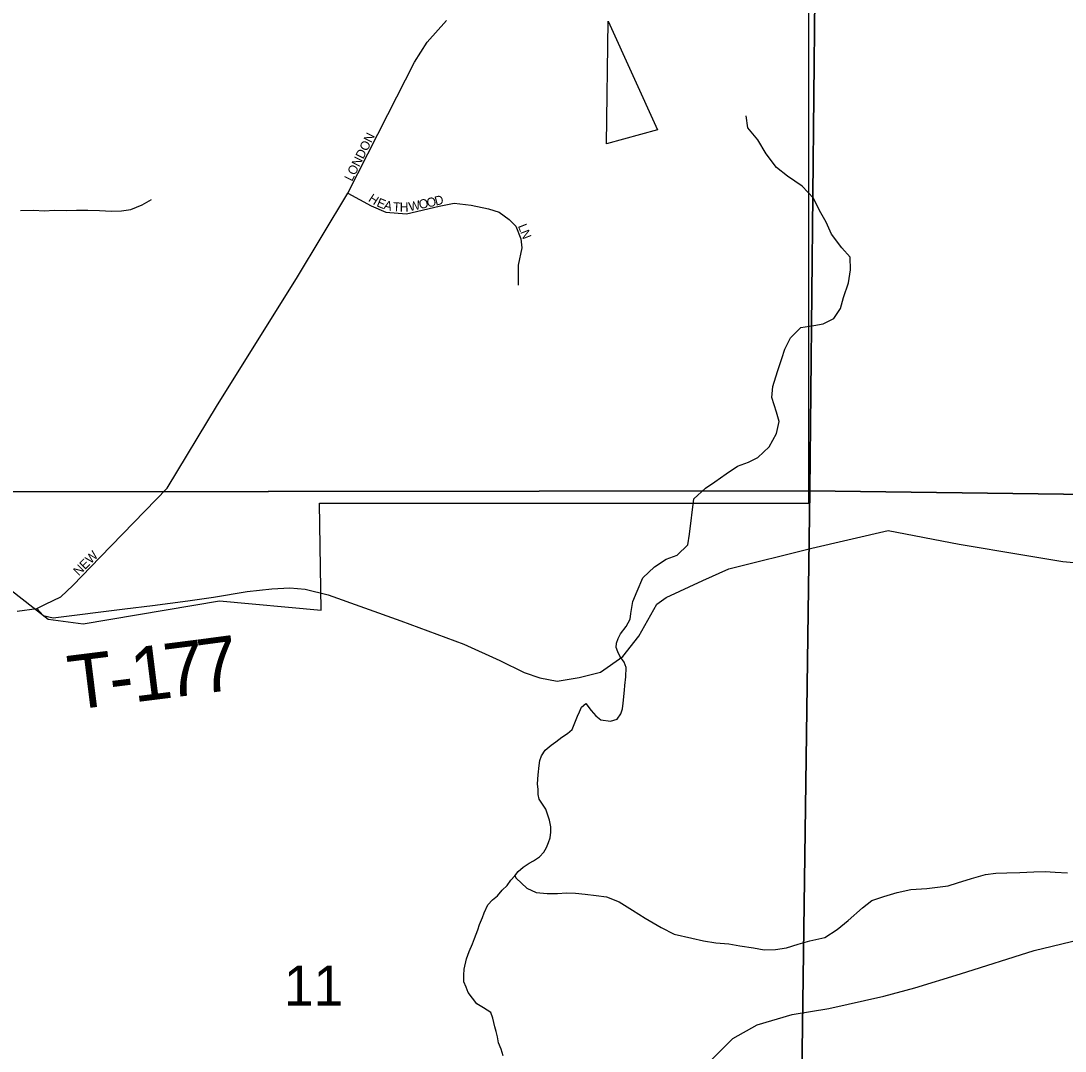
# Model space of a CAD drawing. Extents: x 0 to 34, y -2.3 to 22.
# Drawn here: x 6.815 to 7.907, y 18.764 to 19.84 of the extents above; entities that cross this region are included whole.
import ezdxf

# ---------------------------------------------------------------- set-up
doc = ezdxf.new("R2010")
doc.units = 0
for name, color, linetype in [('GM_X_City_Street', 7, 'Continuous'), ('GM_X_City_Street_Text', 7, 'Continuous'), ('GM_X_Corporation', 7, 'Continuous'), ('GM_X_County_Road', 7, 'Continuous'), ('GM_X_Minor_River', 7, 'Continuous'), ('GM_X_Section', 7, 'Continuous'), ('GM_X_Section_Text', 7, 'Continuous'), ('GM_X_Township_Road', 7, 'Continuous'), ('GM_X_Township_Road_Text', 7, 'Continuous')]:
    doc.layers.add(name, color=color, linetype=linetype)

msp = doc.modelspace()

# ---------------------------------------------------------------- linework, layer by layer
at = {"layer": 'GM_X_City_Street'}
for p, q in [((7.2401, 19.8181), (7.2603, 19.8406)), ((7.2266, 19.7972), (7.2401, 19.8181)), ((7.1989, 19.7426), (7.2266, 19.7972)), ((7.1572, 19.6603), (7.1989, 19.7426)), ((7.1034, 19.5711), (7.1572, 19.6603)), ((7.1572, 19.6603), (7.1815, 19.647)), ((7.1815, 19.647), (7.1969, 19.6405)), ((7.1969, 19.6405), (7.2182, 19.6386)), ((7.2182, 19.6386), (7.2526, 19.6466)), ((7.2526, 19.6466), (7.2681, 19.6498)), ((7.2681, 19.6498), (7.2859, 19.6478)), ((7.2859, 19.6478), (7.304, 19.6438)), ((7.304, 19.6438), (7.3153, 19.6403)), ((7.3153, 19.6403), (7.3257, 19.6328)), ((7.3257, 19.6328), (7.3327, 19.6257)), ((7.3327, 19.6257), (7.3377, 19.6126)), ((7.3377, 19.6126), (7.339, 19.6031)), ((7.339, 19.6031), (7.3351, 19.5851)), ((7.3351, 19.5851), (7.3351, 19.5642)), ((7.0209, 19.4392), (7.1034, 19.5711)), ((6.9683, 19.3521), (7.0209, 19.4392)), ((6.8982, 19.2799), (6.9683, 19.3521)), ((6.8698, 19.2501), (6.8982, 19.2799)), ((6.8573, 19.2385), (6.8698, 19.2501)), ((6.8413, 19.2307), (6.8573, 19.2385))]:
    msp.add_line(p, q, dxfattribs=at)
at = {"layer": 'GM_X_Corporation'}
for points in [[(6.7701, 19.2725), (6.8438, 19.2151), (6.8806, 19.2101), (7.0229, 19.2342), (7.1292, 19.2244), (7.1274, 19.3364), (7.6387, 19.3364), (7.6388, 20.075), (7.7148, 20.075), (7.7148, 20.217), (7.7814, 20.2892), (7.8572, 20.3839), (7.8729, 20.4123), (7.9045, 20.4123), (7.8951, 20.4454), (7.9466, 20.4977)], [(7.429, 19.8401), (7.4807, 19.7264), (7.4275, 19.7119), (7.429, 19.8401)]]:
    msp.add_lwpolyline(points, dxfattribs=at)
at = {"layer": 'GM_X_County_Road'}
for p, q in [((6.8116, 19.2234), (6.8322, 19.2262)), ((6.8322, 19.2262), (6.8413, 19.2307))]:
    msp.add_line(p, q, dxfattribs=at)
at = {"layer": 'GM_X_Minor_River'}
for p, q in [((7.5749, 19.7285), (7.5734, 19.7411)), ((7.5855, 19.716), (7.5749, 19.7285)), ((7.5941, 19.7013), (7.5855, 19.716)), ((7.605, 19.6873), (7.5941, 19.7013)), ((7.6165, 19.6782), (7.605, 19.6873)), ((7.6317, 19.6675), (7.6165, 19.6782)), ((7.6435, 19.655), (7.6317, 19.6675)), ((6.9422, 19.648), (6.9518, 19.6537)), ((7.6499, 19.6422), (7.6435, 19.655)), ((6.815, 19.6421), (6.8286, 19.6424)), ((6.8286, 19.6424), (6.84, 19.642)), ((6.84, 19.642), (6.8503, 19.6425)), ((6.8503, 19.6425), (6.8635, 19.6421)), ((6.8635, 19.6421), (6.8734, 19.6425)), ((6.8734, 19.6425), (6.8855, 19.6425)), ((6.8855, 19.6425), (6.8976, 19.6421)), ((6.8976, 19.6421), (6.9101, 19.6414)), ((6.9101, 19.6414), (6.9204, 19.6418)), ((6.9204, 19.6418), (6.9303, 19.6434)), ((6.9303, 19.6434), (6.9422, 19.648)), ((7.6567, 19.6299), (7.6499, 19.6422)), ((7.6624, 19.6176), (7.6567, 19.6299)), ((7.6733, 19.6032), (7.6624, 19.6176)), ((7.6821, 19.5934), (7.6733, 19.6032)), ((7.6824, 19.5801), (7.6821, 19.5934)), ((7.6801, 19.5665), (7.6824, 19.5801)), ((7.6751, 19.5511), (7.6801, 19.5665)), ((7.6717, 19.5398), (7.6751, 19.5511)), ((7.6649, 19.5294), (7.6717, 19.5398)), ((7.6305, 19.5198), (7.6438, 19.5221)), ((7.6438, 19.5221), (7.6537, 19.5237)), ((7.6537, 19.5237), (7.6649, 19.5294)), ((7.6195, 19.5092), (7.6305, 19.5198)), ((7.6138, 19.4972), (7.6195, 19.5092)), ((7.6059, 19.4739), (7.6105, 19.4874)), ((7.6105, 19.4874), (7.6138, 19.4972)), ((7.6012, 19.4581), (7.6059, 19.4739)), ((7.6001, 19.4468), (7.6012, 19.4581)), ((7.605, 19.4314), (7.6001, 19.4468)), ((7.6077, 19.4218), (7.605, 19.4314)), ((7.605, 19.409), (7.6077, 19.4218)), ((7.5974, 19.3952), (7.605, 19.409)), ((7.5853, 19.3842), (7.5974, 19.3952)), ((7.5641, 19.375), (7.5756, 19.3792)), ((7.5756, 19.3792), (7.5853, 19.3842)), ((7.5525, 19.367), (7.5641, 19.375)), ((7.5308, 19.3521), (7.5405, 19.3586)), ((7.5405, 19.3586), (7.5525, 19.367)), ((7.5187, 19.3407), (7.5308, 19.3521)), ((7.5141, 19.304), (7.5187, 19.3407)), ((7.5123, 19.2927), (7.5141, 19.304)), ((7.5013, 19.282), (7.5123, 19.2927)), ((7.4898, 19.2778), (7.5013, 19.282)), ((7.4653, 19.2581), (7.4774, 19.2699)), ((7.4774, 19.2699), (7.4898, 19.2778)), ((7.4592, 19.2442), (7.4653, 19.2581)), ((7.455, 19.2334), (7.4592, 19.2442)), ((7.4527, 19.2209), (7.455, 19.2334)), ((7.4479, 19.2074), (7.4522, 19.2149)), ((7.4522, 19.2149), (7.4527, 19.2209)), ((7.4419, 19.1999), (7.4479, 19.2074)), ((7.4379, 19.1901), (7.4395, 19.195)), ((7.4395, 19.195), (7.4419, 19.1999)), ((7.4374, 19.1856), (7.4379, 19.1901)), ((7.4392, 19.181), (7.4374, 19.1856)), ((7.4413, 19.1763), (7.4392, 19.181)), ((7.4457, 19.1701), (7.4413, 19.1763)), ((7.4479, 19.1644), (7.4457, 19.1701)), ((7.4476, 19.1549), (7.4479, 19.1644)), ((7.4466, 19.1458), (7.4476, 19.1549)), ((7.4446, 19.1272), (7.4461, 19.1408)), ((7.4461, 19.1408), (7.4466, 19.1458)), ((7.3971, 19.1136), (7.3991, 19.1181)), ((7.3991, 19.1181), (7.4011, 19.123)), ((7.4011, 19.123), (7.4058, 19.127)), ((7.4058, 19.127), (7.4113, 19.1197)), ((7.4113, 19.1197), (7.4161, 19.1142)), ((7.4424, 19.1162), (7.4441, 19.1215)), ((7.4441, 19.1215), (7.4446, 19.1272)), ((7.3914, 19.0996), (7.395, 19.1083)), ((7.395, 19.1083), (7.3971, 19.1136)), ((7.4161, 19.1142), (7.4213, 19.1099)), ((7.4213, 19.1099), (7.4315, 19.1085)), ((7.4315, 19.1085), (7.4384, 19.1106)), ((7.4384, 19.1106), (7.4424, 19.1162)), ((7.3805, 19.0919), (7.3867, 19.0956)), ((7.3867, 19.0956), (7.3914, 19.0996)), ((7.3696, 19.0835), (7.3743, 19.0868)), ((7.3743, 19.0868), (7.3805, 19.0919)), ((7.3594, 19.0723), (7.3634, 19.0783)), ((7.3634, 19.0783), (7.3696, 19.0835)), ((7.3559, 19.0522), (7.3569, 19.0621)), ((7.3569, 19.0621), (7.3578, 19.0674)), ((7.3578, 19.0674), (7.3594, 19.0723)), ((7.3557, 19.0477), (7.3559, 19.0522)), ((7.3552, 19.0427), (7.3557, 19.0477)), ((7.3559, 19.0374), (7.3552, 19.0427)), ((7.3561, 19.0317), (7.3559, 19.0374)), ((7.3571, 19.0271), (7.3561, 19.0317)), ((7.3641, 19.0166), (7.3571, 19.0271)), ((7.3679, 19.0051), (7.3641, 19.0166)), ((7.3693, 18.9979), (7.3679, 19.0051)), ((7.3691, 18.9925), (7.3693, 18.9979)), ((7.3666, 18.9816), (7.3686, 18.9865)), ((7.3686, 18.9865), (7.3691, 18.9925)), ((7.3617, 18.9714), (7.3645, 18.9763)), ((7.3645, 18.9763), (7.3666, 18.9816)), ((7.3512, 18.9626), (7.3574, 18.9666)), ((7.3574, 18.9666), (7.3617, 18.9714)), ((7.3349, 18.9512), (7.3404, 18.956)), ((7.3404, 18.956), (7.3466, 18.96)), ((7.3466, 18.96), (7.3512, 18.9626)), ((7.3235, 18.9367), (7.3275, 18.9423)), ((7.3275, 18.9423), (7.3314, 18.9467)), ((7.3314, 18.9467), (7.3349, 18.9512)), ((7.3314, 18.9467), (7.3328, 18.9444)), ((7.3328, 18.9444), (7.3442, 18.9338)), ((7.794, 18.9395), (7.8086, 18.9441)), ((7.8086, 18.9441), (7.8235, 18.9482)), ((7.8235, 18.9482), (7.8342, 18.9495)), ((7.8342, 18.9495), (7.8456, 18.9499)), ((7.8456, 18.9499), (7.8593, 18.9503)), ((7.8593, 18.9503), (7.8738, 18.9511)), ((7.8738, 18.9511), (7.8856, 18.9515)), ((7.8856, 18.9515), (7.8962, 18.9508)), ((7.8962, 18.9508), (7.9091, 18.9501)), ((7.3133, 18.9259), (7.3184, 18.9318)), ((7.3184, 18.9318), (7.3235, 18.9367)), ((7.3442, 18.9338), (7.354, 18.9293)), ((7.731, 18.9294), (7.7452, 18.9325)), ((7.7452, 18.9325), (7.7619, 18.9335)), ((7.7619, 18.9335), (7.7844, 18.9364)), ((7.7844, 18.9364), (7.794, 18.9395)), ((7.3032, 18.9166), (7.3083, 18.9218)), ((7.3083, 18.9218), (7.3133, 18.9259)), ((7.354, 18.9293), (7.3654, 18.9283)), ((7.3654, 18.9283), (7.376, 18.9284)), ((7.376, 18.9284), (7.3855, 18.9289)), ((7.3855, 18.9289), (7.395, 18.9286)), ((7.395, 18.9286), (7.4049, 18.9276)), ((7.4049, 18.9276), (7.4166, 18.9261)), ((7.4166, 18.9261), (7.4272, 18.9247)), ((7.4272, 18.9247), (7.4404, 18.9198)), ((7.6949, 18.9133), (7.7046, 18.921)), ((7.7046, 18.921), (7.7172, 18.9252)), ((7.7172, 18.9252), (7.731, 18.9294)), ((7.2996, 18.908), (7.3032, 18.9166)), ((7.4404, 18.9198), (7.4546, 18.911)), ((7.4546, 18.911), (7.4677, 18.9027)), ((7.6797, 18.9), (7.6949, 18.9133)), ((7.2947, 18.8959), (7.2979, 18.9031)), ((7.2979, 18.9031), (7.2996, 18.908)), ((7.4677, 18.9027), (7.4845, 18.8927)), ((7.6684, 18.8908), (7.6797, 18.9)), ((7.2893, 18.8812), (7.293, 18.8903)), ((7.293, 18.8903), (7.2947, 18.8959)), ((7.4845, 18.8927), (7.498, 18.8859)), ((7.6556, 18.8824), (7.6684, 18.8908)), ((7.2873, 18.8756), (7.2893, 18.8812)), ((7.498, 18.8859), (7.5165, 18.8816)), ((7.5165, 18.8816), (7.5286, 18.879)), ((7.5286, 18.879), (7.5414, 18.8767)), ((7.5414, 18.8767), (7.5551, 18.8756)), ((7.6277, 18.8755), (7.6399, 18.879)), ((7.6399, 18.879), (7.6556, 18.8824)), ((7.2812, 18.8601), (7.2837, 18.8677)), ((7.2837, 18.8677), (7.2873, 18.8756)), ((7.5551, 18.8756), (7.5668, 18.8737)), ((7.5668, 18.8737), (7.5808, 18.8715)), ((7.5808, 18.8715), (7.5922, 18.8696)), ((7.5922, 18.8696), (7.604, 18.8697)), ((7.604, 18.8697), (7.6154, 18.8717)), ((7.6154, 18.8717), (7.6277, 18.8755)), ((7.2786, 18.8492), (7.2812, 18.8601)), ((7.2781, 18.8431), (7.2786, 18.8492)), ((7.2782, 18.8359), (7.2781, 18.8431)), ((7.2808, 18.8305), (7.2782, 18.8359)), ((7.2829, 18.8247), (7.2808, 18.8305)), ((7.2917, 18.8131), (7.2829, 18.8247)), ((7.2988, 18.8087), (7.2917, 18.8131)), ((7.3063, 18.8039), (7.2988, 18.8087)), ((7.3084, 18.7982), (7.3063, 18.8039)), ((7.3105, 18.789), (7.3084, 18.7982)), ((7.3119, 18.784), (7.3105, 18.789)), ((7.3133, 18.7787), (7.3119, 18.784)), ((7.3146, 18.7722), (7.3133, 18.7787)), ((7.3171, 18.7656), (7.3146, 18.7722)), ((7.3192, 18.7587), (7.3171, 18.7656))]:
    msp.add_line(p, q, dxfattribs=at)
at = {"layer": 'GM_X_Section'}
for p, q in [((7.6503, 20.3564), (7.6398, 19.3493)), ((7.6398, 19.3493), (7.6503, 20.3564)), ((7.6398, 19.3493), (6.6178, 19.348)), ((6.6178, 19.348), (7.6398, 19.3493)), ((7.6398, 19.3493), (7.6261, 18.3379)), ((7.6261, 18.3379), (7.6398, 19.3493)), ((8.6506, 19.3353), (7.6398, 19.3493)), ((7.6398, 19.3493), (8.6506, 19.3353))]:
    msp.add_line(p, q, dxfattribs=at)
at = {"layer": 'GM_X_Township_Road'}
for p, q in [((7.6418, 19.2894), (7.7215, 19.3079)), ((7.7215, 19.3079), (7.7959, 19.2935)), ((7.7959, 19.2935), (7.8623, 19.2823)), ((7.555, 19.2677), (7.6418, 19.2894)), ((7.8623, 19.2823), (7.904, 19.2755)), ((7.904, 19.2755), (8.0026, 19.2655)), ((7.5279, 19.2554), (7.555, 19.2677)), ((7.0777, 19.2468), (7.0966, 19.2479)), ((7.0966, 19.2479), (7.1125, 19.2464)), ((7.4896, 19.2376), (7.5279, 19.2554)), ((6.9898, 19.2342), (7.0168, 19.238)), ((7.0168, 19.238), (7.0519, 19.244)), ((7.0519, 19.244), (7.0777, 19.2468)), ((7.1125, 19.2464), (7.1365, 19.2404)), ((7.1365, 19.2404), (7.1366, 19.2404)), ((7.1366, 19.2404), (7.2124, 19.2133)), ((7.48, 19.2307), (7.4896, 19.2376)), ((6.8322, 19.2262), (6.8387, 19.2189)), ((6.8492, 19.2163), (6.924, 19.226)), ((6.924, 19.226), (6.9528, 19.2294)), ((6.9528, 19.2294), (6.9898, 19.2342)), ((7.461, 19.1974), (7.48, 19.2307)), ((6.8387, 19.2189), (6.8492, 19.2163)), ((7.2124, 19.2133), (7.2782, 19.1888)), ((7.4443, 19.1761), (7.461, 19.1974)), ((7.2782, 19.1888), (7.3158, 19.172)), ((7.3158, 19.172), (7.3413, 19.1594)), ((7.4209, 19.1598), (7.4443, 19.1761)), ((7.3413, 19.1594), (7.3575, 19.1536)), ((7.3575, 19.1536), (7.3757, 19.1501)), ((7.3757, 19.1501), (7.3987, 19.154)), ((7.3987, 19.154), (7.4209, 19.1598)), ((7.8742, 18.8687), (7.922, 18.8804)), ((7.7971, 18.8445), (7.8742, 18.8687)), ((7.7494, 18.8297), (7.7971, 18.8445)), ((7.717, 18.8209), (7.7494, 18.8297)), ((7.6595, 18.8083), (7.717, 18.8209)), ((7.5846, 18.7912), (7.6212, 18.8019)), ((7.6212, 18.8019), (7.6595, 18.8083)), ((7.5593, 18.7767), (7.5846, 18.7912)), ((7.5351, 18.7524), (7.5593, 18.7767))]:
    msp.add_line(p, q, dxfattribs=at)

# ---------------------------------------------------------------- texts
at = {"layer": 'GM_X_City_Street_Text'}
for s, rotation, p in [('LONDON', 63.4349, (7.1614, 19.672)), ('H', 326.7313, (7.1777, 19.6524)), ('E', 337.9112, (7.1864, 19.6469)), ('A', 345.4395, (7.1939, 19.6439)), ('W', 11.8791, (7.2217, 19.6413)), ('O', 12.146, (7.2323, 19.6436)), ('O', 12.1341, (7.2405, 19.6453)), ('D', 14.66, (7.2491, 19.6472)), ('T', 356.2729, (7.2039, 19.6415)), ('H', 0.2997, (7.2113, 19.6411)), ('L', 291.6784, (7.3346, 19.626)), ('N', 291.1226, (7.3371, 19.6198)), ('NEW', 44.9976, (6.8759, 19.2599))]:
    msp.add_text(s, height=0.00947, rotation=rotation, dxfattribs=at).set_placement(p)
at = {"layer": 'GM_X_Section_Text'}
msp.add_text('11', height=0.04186, rotation=0, dxfattribs=at).set_placement((7.0901, 18.8112))
at = {"layer": 'GM_X_Township_Road_Text'}
for s, rotation, p in [('7', 7.2106, (6.9687, 19.1325)), ('7', 7.6187, (7.0038, 19.1369)), ('1', 7.1176, (6.9338, 19.1281)), ('T', 7.0893, (6.8685, 19.12)), ('-', 7.0974, (6.9107, 19.1252))]:
    msp.add_text(s, height=0.0568, rotation=rotation, dxfattribs=at).set_placement(p)

doc.saveas('drawing.dxf')
